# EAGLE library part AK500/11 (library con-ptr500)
CONNECTOR
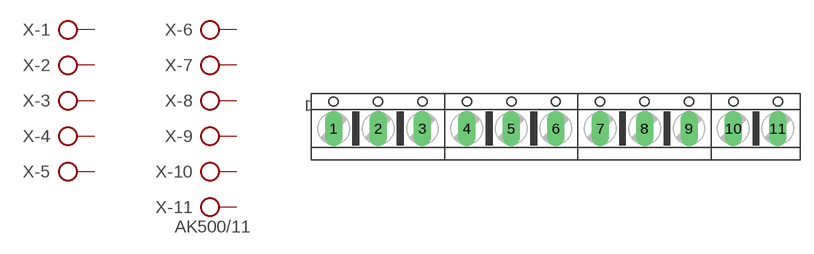
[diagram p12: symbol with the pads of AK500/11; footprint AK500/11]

Designator prefix X; gates -1=KL -2=KL -3=KL -4=KL -5=KL -6=KL -7=KL -8=KL -9=KL -10=KL -11=KLV

## AK500/11 (OC_FARNELL: unknown; OC_NEWARK: unknown)  [AK500/11]
1  -1:KL  pas
2  -2:KL  pas
3  -3:KL  pas
4  -4:KL  pas
5  -5:KL  pas
6  -6:KL  pas
7  -7:KL  pas
8  -8:KL  pas
9  -9:KL  pas
10  -10:KL  pas
11  -11:KL  pas

## Footprint AK500/11 (pad centres in mm)
CONNECTOR
drill 1.321 long: 1 -25.019,0; 2 -20.015,0; 3 -15.011,0; 4 -10.008,0; 5 -5.004,0; 6 0,0; 7 5.004,0; 8 10.008,0; 9 15.011,0; 10 20.015,0; 11 25.019,0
